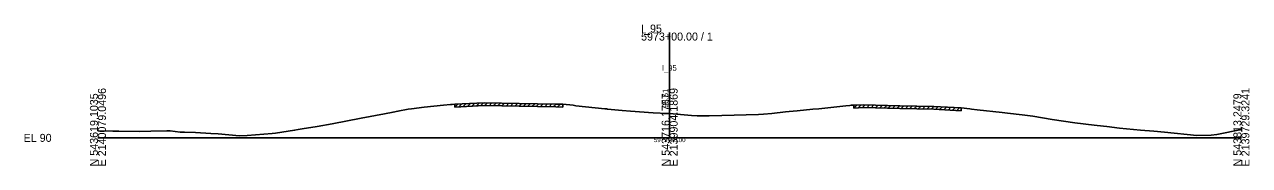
# Model space of a CAD drawing. Extents: x -12534 to 3403, y -1332 to 21983.
# Drawn here: x -25.7 to 402.8, y 7990.3 to 8039.7 of the extents above; entities that cross this region are included whole.
import ezdxf

# ---------------------------------------------------------------- set-up
doc = ezdxf.new("R2010")
doc.units = 0
for name, color, linetype in [('RD_GPK_XS_Cell', 7, 'Continuous'), ('RD_XS_ExGround', 7, 'Continuous'), ('RD_XS_ExPaveRet', 7, 'Continuous'), ('RD_XS_TX_Baseline', 7, 'Continuous'), ('RD_XS_TX_Elev_EX', 7, 'Continuous'), ('RD_XS_TX_Station', 7, 'Continuous')]:
    doc.layers.add(name, color=color, linetype=linetype)

msp = doc.modelspace()

# ---------------------------------------------------------------- linework, layer by layer
at = {"layer": 'RD_GPK_XS_Cell'}
for p, q in [((200, 8000), (200, 8036.9)), ((0, 8000), (200, 8000)), ((200, 8000), (400, 8000))]:
    msp.add_line(p, q, dxfattribs=at)
at = {"layer": 'RD_XS_ExGround'}
msp.add_lwpolyline([(0, 8002.49), (5.22, 8002.37), (6.77, 8002.37), (7.32, 8002.35), (14.64, 8002.27), (18.46, 8002.34), (24.1, 8002.49), (25.29, 8002.41), (28.78, 8002.03), (30.28, 8002.02), (34.14, 8001.84), (39.51, 8001.58), (42.11, 8001.42), (49.5, 8000.72), (52.19, 8000.84), (60.99, 8001.5), (62.09, 8001.66), (68.79, 8002.67), (70.01, 8002.92), (71.43, 8003.14), (76.73, 8004.01), (81.9, 8004.92), (92.07, 8006.88), (100.21, 8008.39), (103.24, 8009.04), (104.91, 8009.34), (108.47, 8010.01), (109.65, 8010.18), (114.1, 8010.78), (120.9, 8011.45), (123.37, 8011.69), (123.91, 8011.72), (124.8, 8011.8), (135.09, 8012.3), (147.32, 8012.08), (160.22, 8011.85), (162.64, 8011.76), (166.23, 8011.41), (167.15, 8011.28), (177.31, 8010.17), (177.85, 8010.12), (178.23, 8010.08), (179.59, 8009.95), (183.35, 8009.6), (186.3, 8009.35), (194.23, 8008.82), (199.19, 8008.58), (200, 8008.51), (207.66, 8007.88), (209.62, 8007.7), (210.78, 8007.72), (213.81, 8007.77), (218.27, 8007.89), (231.11, 8008.24), (232.81, 8008.33), (235.73, 8008.55), (240.49, 8009.09), (241.84, 8009.25), (244.66, 8009.52), (250.03, 8010.04), (252.18, 8010.23), (261.66, 8011.24), (263.08, 8011.4), (263.49, 8011.43), (264.45, 8011.45), (267.72, 8011.62), (280.51, 8011.27), (292.4, 8011.02), (302, 8010.52), (305.03, 8010.13), (305.6, 8010.08), (307.61, 8009.87), (316.34, 8008.88), (318.24, 8008.66), (323.34, 8008.03), (326.07, 8007.7), (327.08, 8007.56), (333.85, 8006.42), (337.81, 8005.8), (341.71, 8005.27), (348.46, 8004.46), (349.6, 8004.35), (352.94, 8003.93), (357.36, 8003.42), (364.7, 8002.73), (369.39, 8002.38), (373.06, 8001.96), (384.38, 8000.8), (389.46, 8000.9), (391.37, 8001.2), (400, 8002.97)], dxfattribs=at)
at = {"layer": 'RD_XS_ExPaveRet'}
for p, q in [((124.8, 8010.8), (125.85, 8011.85)), ((124.8, 8010.8), (124.8, 8011.8)), ((124.8, 8010.8), (135.09, 8011.3)), ((126.3, 8010.87), (127.35, 8011.92)), ((127.8, 8010.94), (128.85, 8011.99)), ((129.3, 8011.02), (130.35, 8012.07)), ((130.8, 8011.09), (131.85, 8012.14)), ((132.3, 8011.16), (133.35, 8012.21)), ((133.8, 8011.24), (134.85, 8012.29)), ((135.09, 8011.3), (147.32, 8011.08)), ((135.3, 8011.3), (136.28, 8012.28)), ((136.8, 8011.27), (137.78, 8012.25)), ((138.3, 8011.24), (139.28, 8012.22)), ((139.8, 8011.21), (140.78, 8012.2)), ((141.3, 8011.19), (142.28, 8012.17)), ((142.8, 8011.16), (143.78, 8012.14)), ((144.3, 8011.13), (145.28, 8012.12)), ((145.8, 8011.11), (146.78, 8012.09)), ((147.3, 8011.08), (148.28, 8012.06)), ((147.32, 8011.08), (160.22, 8010.85)), ((148.8, 8011.05), (149.78, 8012.04)), ((150.3, 8011.03), (151.28, 8012.01)), ((151.8, 8011), (152.78, 8011.98)), ((153.3, 8010.97), (154.28, 8011.96)), ((154.8, 8010.95), (155.78, 8011.93)), ((156.3, 8010.92), (157.28, 8011.91)), ((157.8, 8010.9), (158.78, 8011.88)), ((159.3, 8010.87), (160.28, 8011.85)), ((160.22, 8010.85), (162.64, 8010.76)), ((160.8, 8010.83), (161.76, 8011.79)), ((162.64, 8011.76), (162.64, 8010.76)), ((264.45, 8010.45), (265.5, 8011.5)), ((264.45, 8010.45), (264.45, 8011.45)), ((264.45, 8010.45), (267.72, 8010.62)), ((265.95, 8010.52), (267, 8011.58)), ((267.45, 8010.6), (268.44, 8011.6)), ((267.72, 8010.62), (280.51, 8010.27)), ((268.95, 8010.58), (269.92, 8011.56)), ((270.45, 8010.54), (271.42, 8011.52)), ((271.95, 8010.5), (272.92, 8011.48)), ((273.45, 8010.46), (274.42, 8011.44)), ((274.95, 8010.42), (275.92, 8011.4)), ((276.45, 8010.38), (277.42, 8011.36)), ((277.95, 8010.34), (278.92, 8011.32)), ((279.45, 8010.3), (280.42, 8011.28)), ((280.51, 8010.27), (292.4, 8010.02)), ((280.95, 8010.27), (281.93, 8011.24)), ((282.45, 8010.23), (283.43, 8011.21)), ((283.95, 8010.2), (284.93, 8011.18)), ((285.45, 8010.17), (286.43, 8011.15)), ((286.95, 8010.14), (287.93, 8011.11)), ((288.45, 8010.1), (289.43, 8011.08)), ((289.95, 8010.07), (290.93, 8011.05)), ((291.45, 8010.04), (292.43, 8011.02)), ((292.4, 8010.02), (302, 8009.52)), ((292.95, 8009.99), (293.9, 8010.94)), ((294.45, 8009.91), (295.4, 8010.86)), ((295.95, 8009.84), (296.9, 8010.79)), ((297.45, 8009.76), (298.4, 8010.71)), ((298.95, 8009.68), (299.9, 8010.63)), ((300.45, 8009.6), (301.4, 8010.56)), ((302, 8010.52), (302, 8009.52))]:
    msp.add_line(p, q, dxfattribs=at)

# ---------------------------------------------------------------- texts
at = {"layer": 'RD_GPK_XS_Cell'}
for s, p in [('I_95', (190, 8036.9)), ('5973+00.00 / 1', (190, 8034.1)), ('EL 90', (-26, 7998.6))]:
    msp.add_text(s, height=2.8, dxfattribs=at).set_placement(p)
for s, p in [('N 543619.1035', (0, 7990)), ('E 2140079.0496', (2.8, 7990)), ('N 543716.1757', (200, 7990)), ('E 2139904.1869', (202.8, 7990)), ('N 543813.2479', (400, 7990)), ('E 2139729.3241', (402.8, 7990))]:
    msp.add_text(s, height=2.8, rotation=90, dxfattribs=at).set_placement(p)
at = {"layer": 'RD_XS_TX_Baseline'}
msp.add_text('I_95', height=2, dxfattribs=at).set_placement((197.28, 8023.51))
at = {"layer": 'RD_XS_TX_Elev_EX'}
msp.add_text('98.51', height=2, rotation=90, dxfattribs=at).set_placement((199.5, 8010.51))
at = {"layer": 'RD_XS_TX_Station'}
msp.add_text('5973+00.00', height=1.5, dxfattribs=at).set_placement((194.54, 7998.51))

doc.saveas('drawing.dxf')
